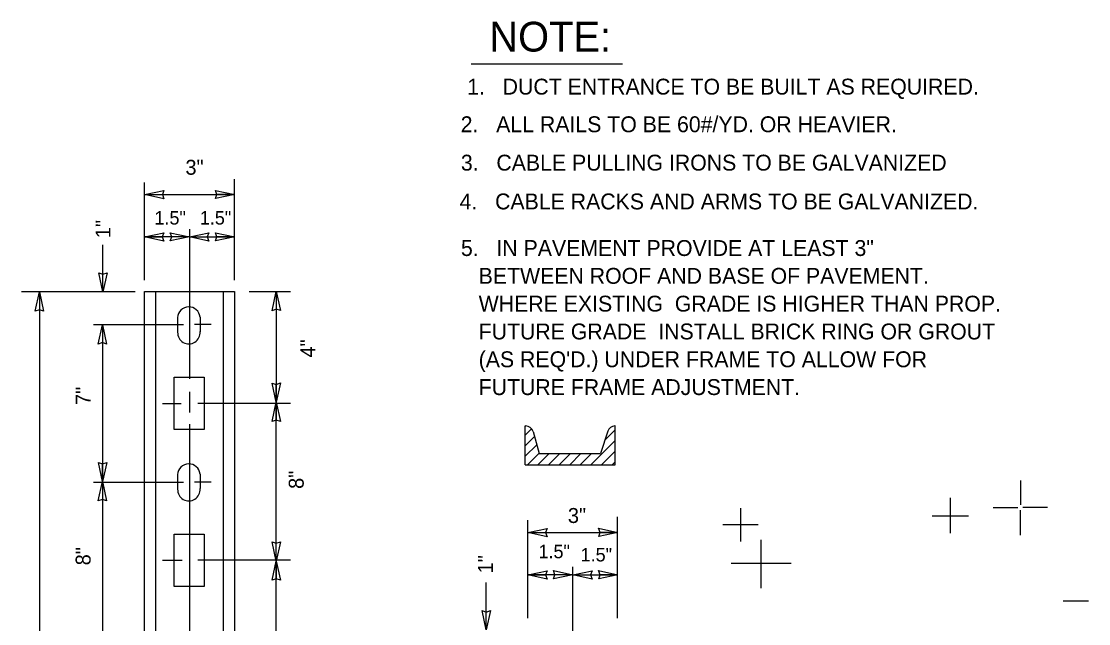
# Model space of a CAD drawing. Extents: x 19188 to 19495, y 20866 to 21061.
# Drawn here: x 19189.8 to 19246, y 20932.9 to 20964.7 of the extents above; entities that cross this region are included whole.
import ezdxf

# ---------------------------------------------------------------- set-up
doc = ezdxf.new("R2010")
doc.units = 0
doc.layers.add('G-ANNO-NOTE', color=7, linetype='Continuous')

msp = doc.modelspace()

# ---------------------------------------------------------------- linework, layer by layer
at = {"layer": 'G-ANNO-NOTE'}
for p, q in [((19213.511, 20962.418), (19221.496, 20962.418)), ((19196.314, 20950.999), (19196.314, 20956.159)), ((19201.043, 20950.999), (19201.043, 20956.336)), ((19196.314, 20955.516), (19201.061, 20955.516)), ((19196.314, 20955.516), (19197.25, 20955.516)), ((19201.061, 20955.516), (19200.125, 20955.516)), ((19194.117, 20950.381), (19194.117, 20952.873)), ((19198.679, 20953.282), (19196.308, 20953.282)), ((19196.308, 20953.282), (19197.244, 20953.282)), ((19198.679, 20953.282), (19197.742, 20953.282)), ((19198.679, 20953.282), (19201.061, 20953.282)), ((19198.679, 20953.282), (19199.615, 20953.282)), ((19201.061, 20953.282), (19200.125, 20953.282)), ((19194.117, 20950.381), (19194.117, 20951.317)), ((19195.811, 20950.381), (19189.822, 20950.381)), ((19190.773, 20950.381), (19190.773, 20894.983)), ((19190.773, 20950.381), (19190.773, 20949.445)), ((19196.314, 20950.408), (19201.043, 20950.408)), ((19196.314, 20894.88), (19196.314, 20950.408)), ((19196.905, 20894.88), (19196.905, 20950.408)), ((19200.452, 20950.408), (19200.452, 20894.88)), ((19201.043, 20950.408), (19201.043, 20894.88)), ((19201.828, 20950.414), (19204.002, 20950.414)), ((19203.255, 20950.414), (19203.255, 20944.564)), ((19203.255, 20950.414), (19203.255, 20949.477)), ((19198.053, 20949.021), (19198.053, 20948.232)), ((19199.236, 20949.057), (19199.236, 20948.288)), ((19193.615, 20948.672), (19198.356, 20948.672)), ((19194.095, 20948.647), (19194.096, 20940.38)), ((19194.095, 20948.647), (19194.095, 20947.711)), ((19199.818, 20948.672), (19198.952, 20948.672)), ((19197.876, 20945.888), (19199.452, 20945.888)), ((19197.876, 20943.129), (19197.876, 20945.888)), ((19199.452, 20945.888), (19199.452, 20943.129)), ((19203.255, 20944.564), (19203.255, 20945.5)), ((19197.261, 20944.509), (19198.248, 20944.509)), ((19204.002, 20944.509), (19199.114, 20944.509)), ((19203.255, 20936.195), (19203.255, 20944.564)), ((19203.255, 20944.564), (19203.255, 20943.628)), ((19216.37, 20941.271), (19216.37, 20943.314)), ((19216.37, 20943.314), (19216.397, 20943.314)), ((19221.1, 20943.314), (19221.087, 20943.314)), ((19221.1, 20941.271), (19221.1, 20943.314)), ((19199.452, 20943.129), (19197.876, 20943.129)), ((19216.37, 20942.833), (19216.703, 20943.165)), ((19216.37, 20942.276), (19216.852, 20942.758)), ((19216.777, 20943.026), (19217.104, 20941.862)), ((19220.712, 20943.04), (19220.332, 20941.862)), ((19220.557, 20942.56), (19221.1, 20943.104)), ((19216.37, 20941.718), (19216.974, 20942.323)), ((19219.825, 20941.271), (19221.1, 20942.546)), ((19216.481, 20941.271), (19217.097, 20941.887)), ((19217.038, 20941.271), (19217.629, 20941.862)), ((19217.104, 20941.862), (19220.332, 20941.862)), ((19217.595, 20941.271), (19218.187, 20941.862)), ((19218.153, 20941.271), (19218.744, 20941.862)), ((19218.71, 20941.271), (19219.301, 20941.862)), ((19219.268, 20941.271), (19219.859, 20941.862)), ((19220.383, 20941.271), (19221.1, 20941.989)), ((19194.096, 20940.38), (19194.096, 20941.316)), ((19216.37, 20941.271), (19221.1, 20941.271)), ((19220.94, 20941.271), (19221.1, 20941.431)), ((19198.053, 20940.743), (19198.053, 20939.955)), ((19199.236, 20940.779), (19199.236, 20940.01)), ((19242.452, 20940.437), (19242.452, 20939.15)), ((19242.452, 20940.437), (19242.452, 20939.15)), ((19193.616, 20940.348), (19198.357, 20940.349)), ((19194.096, 20940.38), (19194.097, 20931.42)), ((19194.096, 20940.38), (19194.096, 20939.443)), ((19199.818, 20940.349), (19198.952, 20940.349)), ((19238.752, 20939.526), (19238.752, 20937.665)), ((19238.752, 20939.526), (19238.752, 20937.665)), ((19227.702, 20938.988), (19227.702, 20937.217)), ((19227.702, 20938.988), (19227.702, 20937.217)), ((19241.016, 20939.015), (19242.313, 20939.015)), ((19241.016, 20939.015), (19242.313, 20939.015)), ((19242.452, 20937.554), (19242.452, 20938.879)), ((19242.452, 20937.554), (19242.452, 20938.879)), ((19243.888, 20939.015), (19242.583, 20939.015)), ((19243.888, 20939.015), (19242.583, 20939.015)), ((19216.507, 20933.183), (19216.507, 20938.344)), ((19221.237, 20933.183), (19221.237, 20938.52)), ((19237.805, 20938.577), (19239.722, 20938.577)), ((19237.805, 20938.577), (19239.722, 20938.577)), ((19197.876, 20937.611), (19199.452, 20937.611)), ((19197.876, 20934.852), (19197.876, 20937.611)), ((19199.452, 20937.611), (19199.452, 20934.852)), ((19216.507, 20937.701), (19221.254, 20937.701)), ((19216.507, 20937.701), (19217.443, 20937.701)), ((19221.254, 20937.701), (19220.318, 20937.701)), ((19228.632, 20938.1), (19226.77, 20938.1)), ((19228.632, 20938.1), (19226.77, 20938.1)), ((19203.255, 20936.195), (19203.255, 20937.132)), ((19228.799, 20934.771), (19228.799, 20937.305)), ((19228.799, 20934.771), (19228.799, 20937.305)), ((19197.261, 20936.231), (19198.302, 20936.231)), ((19204.002, 20936.231), (19199.114, 20936.231)), ((19203.255, 20927.363), (19203.255, 20936.195)), ((19203.255, 20936.195), (19203.255, 20935.259)), ((19227.221, 20936.075), (19230.369, 20936.075)), ((19227.221, 20936.075), (19230.369, 20936.075)), ((19218.872, 20935.467), (19216.501, 20935.467)), ((19216.501, 20935.467), (19217.437, 20935.467)), ((19218.872, 20935.467), (19217.936, 20935.467)), ((19218.872, 20935.467), (19221.254, 20935.467)), ((19218.872, 20935.467), (19219.808, 20935.467)), ((19221.254, 20935.467), (19220.318, 20935.467)), ((19199.452, 20934.852), (19197.876, 20934.852)), ((19214.31, 20932.566), (19214.31, 20935.058)), ((19244.711, 20934.094), (19246.05, 20934.094)), ((19244.711, 20934.094), (19246.05, 20934.094)), ((19214.31, 20932.566), (19214.31, 20933.502))]:
    msp.add_line(p, q, dxfattribs=at)
for points in [[(19197.25, 20955.517), (19197.332, 20955.292), (19196.314, 20955.516), (19197.33, 20955.73), (19197.25, 20955.517)], [(19200.125, 20955.516), (19200.043, 20955.74), (19201.061, 20955.516), (19200.045, 20955.302), (19200.125, 20955.516)], [(19197.244, 20953.282), (19197.326, 20953.059), (19196.308, 20953.282), (19197.324, 20953.496), (19197.244, 20953.282)], [(19197.742, 20953.282), (19197.66, 20953.506), (19198.679, 20953.282), (19197.662, 20953.069), (19197.742, 20953.282)], [(19198.679, 20953.701), (19198.679, 20945.793)], [(19199.615, 20953.282), (19199.697, 20953.059), (19198.679, 20953.282), (19199.695, 20953.496), (19199.615, 20953.282)], [(19200.125, 20953.282), (19200.043, 20953.506), (19201.061, 20953.282), (19200.045, 20953.069), (19200.125, 20953.282)], [(19194.117, 20951.317), (19194.341, 20951.399), (19194.117, 20950.381), (19193.903, 20951.397), (19194.117, 20951.317)], [(19190.773, 20949.445), (19190.549, 20949.363), (19190.773, 20950.381), (19190.986, 20949.365), (19190.773, 20949.445)], [(19203.255, 20949.477), (19203.031, 20949.395), (19203.255, 20950.414), (19203.469, 20949.397), (19203.255, 20949.477)], [(19194.096, 20947.711), (19193.872, 20947.629), (19194.095, 20948.647), (19194.309, 20947.631), (19194.096, 20947.711)], [(19203.255, 20945.5), (19203.479, 20945.582), (19203.255, 20944.564), (19203.041, 20945.58), (19203.255, 20945.5)], [(19198.679, 20945.111), (19198.679, 20944.019)], [(19203.255, 20943.628), (19203.031, 20943.546), (19203.255, 20944.564), (19203.469, 20943.548), (19203.255, 20943.628)], [(19198.679, 20943.419), (19198.679, 20938.656)], [(19194.096, 20941.316), (19194.32, 20941.398), (19194.096, 20940.38), (19193.883, 20941.396), (19194.096, 20941.316)], [(19194.096, 20939.443), (19193.873, 20939.361), (19194.096, 20940.38), (19194.31, 20939.363), (19194.096, 20939.443)], [(19198.679, 20938.656), (19198.679, 20930.749)], [(19217.443, 20937.701), (19217.525, 20937.477), (19216.507, 20937.701), (19217.523, 20937.915), (19217.443, 20937.701)], [(19220.318, 20937.701), (19220.236, 20937.925), (19221.254, 20937.701), (19220.238, 20937.487), (19220.318, 20937.701)], [(19203.255, 20937.132), (19203.479, 20937.214), (19203.255, 20936.195), (19203.041, 20937.211), (19203.255, 20937.132)], [(19203.255, 20935.259), (19203.031, 20935.177), (19203.255, 20936.195), (19203.469, 20935.179), (19203.255, 20935.259)], [(19217.437, 20935.467), (19217.519, 20935.243), (19216.501, 20935.467), (19217.517, 20935.681), (19217.437, 20935.467)], [(19217.935, 20935.467), (19217.853, 20935.691), (19218.872, 20935.467), (19217.856, 20935.253), (19217.935, 20935.467)], [(19218.872, 20931.451), (19218.872, 20935.886)], [(19219.808, 20935.467), (19219.89, 20935.243), (19218.872, 20935.467), (19219.888, 20935.681), (19219.808, 20935.467)], [(19220.318, 20935.467), (19220.236, 20935.691), (19221.254, 20935.467), (19220.238, 20935.253), (19220.318, 20935.467)], [(19214.31, 20933.503), (19214.534, 20933.584), (19214.31, 20932.566), (19214.097, 20933.582), (19214.31, 20933.503)]]:
    msp.add_lwpolyline(points, dxfattribs=at)
for centre, radius, start, end in [((19198.647, 20949.002), 0.591, 5.267, 177.6123), ((19198.647, 20948.234), 0.591, 177.6721, 5.267), ((19216.398, 20942.92), 0.394, 15.6655, 90), ((19221.087, 20942.92), 0.394, 90, 162.142), ((19198.647, 20940.725), 0.591, 5.267, 177.6123), ((19198.647, 20939.956), 0.591, 177.6721, 5.267)]:
    msp.add_arc(centre, radius, start, end, dxfattribs=at)

# ---------------------------------------------------------------- texts
for s, height, p in [('NOTE:', 1.571, (19214.473, 20963.058)), ('1.   DUCT ENTRANCE TO BE BUILT AS REQUIRED.', 0.83786, (19213.31, 20960.789)), ('2.   ALL RAILS TO BE 60#/YD. OR HEAVIER.', 0.83786, (19212.968, 20958.805)), ('3"', 0.7883, (19198.466, 20956.561)), ('3.   CABLE PULLING IRONS TO BE GALVANIZED', 0.83786, (19212.979, 20956.781)), ('4.   CABLE RACKS AND ARMS TO BE GALVANIZED.', 0.83786, (19212.911, 20954.735)), ('1.5"', 0.7095, (19196.833, 20953.935)), ('1.5"', 0.7095, (19199.223, 20953.935)), ('5.   IN PAVEMENT PROVIDE AT LEAST 3"', 0.83785, (19212.981, 20952.279)), ('   BETWEEN ROOF AND BASE OF PAVEMENT. ', 0.83785, (19212.981, 20950.812)), ('   WHERE EXISTING  GRADE IS HIGHER THAN PROP. ', 0.83785, (19212.981, 20949.346)), ('   FUTURE GRADE  INSTALL BRICK RING OR GROUT', 0.83785, (19212.981, 20947.879)), ("   (AS REQ'D.) UNDER FRAME TO ALLOW FOR ", 0.83785, (19212.981, 20946.413)), ('   FUTURE FRAME ADJUSTMENT.', 0.83785, (19212.981, 20944.946)), ('3"', 0.7883, (19218.613, 20938.2)), ('1.5"', 0.7095, (19217.065, 20936.342)), ('1.5"', 0.7095, (19219.285, 20936.172))]:
    msp.add_text(s, height=height, dxfattribs=at).set_placement(p)
for s, p in [('1"', (19194.517, 20953.219)), ('4"', (19205.304, 20946.923)), ('7"', (19193.471, 20944.421)), ('8"', (19204.696, 20939.997)), ('8"', (19193.47, 20935.967)), ('1"', (19214.665, 20935.541))]:
    msp.add_text(s, height=0.7883, rotation=90, dxfattribs=at).set_placement(p)

doc.saveas('drawing.dxf')
